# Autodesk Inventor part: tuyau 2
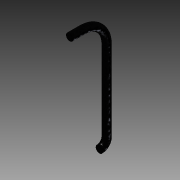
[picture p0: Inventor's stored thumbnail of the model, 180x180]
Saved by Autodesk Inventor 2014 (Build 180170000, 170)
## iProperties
Created: 2015-09
Part Number: tuyau 2
Material: Générique
Document SubType Name: Modeling
Designer: OL
Density: 1 g/cm^3
Appearance: Par défaut
Author: OL
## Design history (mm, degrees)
sketch "Esquisse1"
  geometry: L1 (0, 0)-(0, 0); L2 (15, 15)-(15, 180); L3 (-35, 230)-(-61, 230); A1 r 15 centre (0, 15) between (0, 0) and (15, 15); A2 r 50 centre (-35, 180) between (15, 180) and (-35, 230); 2 further points
  constraints: 6 end point, 4 point on circle, 4 point on line, 4 tangent, 2 centre point, 1 horizontal, 1 parallel, 1 perpendicular
  dimensions: "d8" = 61 horizontal distance of L1.start L3.end; "d9" = 15 distance of L1.start point (15, 0); "d10" = 230 distance of point (15, 0) point (15, 230); "d11" = 15 radius of A1; "d12" = 50 radius of A2
sketch "Esquisse2"
  geometry: C1 r 7.5 at (0, 0); 1 further point
  constraints: 1 centre point, 1 coincident
  dimensions: "d4" = 15 diameter of C1
feature "Balayage1" sketch "Esquisse1", "Esquisse2" dims "d6" = 0
node "Solide1"
